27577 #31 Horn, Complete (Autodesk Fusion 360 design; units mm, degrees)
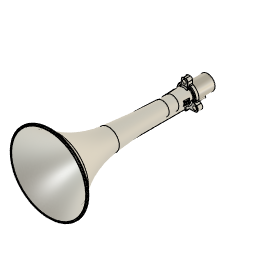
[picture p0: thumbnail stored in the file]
parameter "Bolt_Hole_Tolerance" = 1.5875 (= "( 1 / 16 ) * 1 in")
parameter "Dowel_Hole_Tolerance" = 0.0248 (= "( 1 / 1024 ) * 1 in")
parameter "d211" = 0.1984 (= "( 1 / 128 ) * 1 in")
canvas "Canvas1"
canvas "Canvas5"
canvas "Canvas7"
sketch "Main Profile" plane through (0, 0, 0) normal (1, 0, 0) x axis (0, 1, 0)
  line L1 (0, -22.225) -> (0, 22.225)
  line L2 (-53.975, 22.225) -> (0, 22.225)
  line L3 (-53.975, 44.45) -> (-53.975, 22.225)
  line L4 (-469.1063, 0) -> (0, 0)
  line L5 (-68.2625, 44.45) -> (-53.975, 44.45)
  line L6 (-53.975, -22.225) -> (0, -22.225)
  line L7 (-53.975, 22.225) -> (-53.975, -22.225)
  line L8 (-53.975, -38.1) -> (-53.975, -22.225)
  line L9 (-68.2625, -38.1) -> (-53.975, -38.1)
  line L10 (-68.2625, 44.45) -> (-68.2625, -38.1)
  line L11 (-133.2599, 16.9308) -> (0, 11.1125)
  line L12 (-63.5, 28.575) -> (-53.975, 28.575)
  line L13 (-63.5, 17.063) -> (-63.5, 28.575)
  line L14 (-133.1214, 20.1027) -> (-63.5, 17.063)
  line L15 (-469.1063, -114.3) -> (-469.1063, 114.3)
  line L16 (-68.2625, 17.2709) -> (-68.2625, 44.45)
  line L17 (9.1828, 34.925) -> (-68.2625, 34.925)
  line L18 (-34.1313, 22.225) -> (-34.1313, -22.225)
  line L19 (-133.2599, -16.9308) -> (0, -11.1125)
  line L20 (-68.2625, -17.2709) -> (-68.2625, -38.1)
  line L21 (-68.2625, -17.2709) -> (-133.1214, -20.1027)
  line L22 (-464.3438, 114.3) -> (-469.1063, 114.3)
  line L23 (-464.3438, 109.7849) -> (-464.3438, 114.3)
  line L24 (-104.775, 20.1844) -> (-63.5, 22.225)
  line L25 (-292.2803, 0) -> (-292.2803, 28.575)
  line L26 (-314.4904, -34.925) -> (-68.2625, -34.925)
  arc A1 centre (-15.2071, 2720.7853) radius 2706.4304 clockwise from (-133.2599, 16.9308) to (-292.2803, 28.575)
  arc A2 centre (-261.4012, 328.6152) radius 301.625 clockwise from (-292.2803, 28.575) to (-469.1063, 109.9002)
  arc A3 centre (-15.2071, 2720.7853) radius 2703.2554 clockwise from (-133.1214, 20.1027) to (-291.9553, 31.7333)
  arc A4 centre (-261.4012, 328.6152) radius 298.45 clockwise from (-291.9553, 31.7333) to (-469.1063, 114.3)
  arc A5 centre (-261.4012, -328.6152) radius 298.45 clockwise from (-469.1063, -114.3) to (-291.9553, -31.7333)
  arc A6 centre (-261.4012, -328.6152) radius 301.625 clockwise from (-469.1063, -109.9002) to (-292.2803, -28.575)
  arc A7 centre (-15.2071, -2720.7853) radius 2703.2554 clockwise from (-291.9553, -31.7333) to (-133.1214, -20.1027)
  arc A8 centre (-15.2071, -2720.7853) radius 2706.4304 clockwise from (-292.2803, -28.575) to (-133.2599, -16.9308)
  arc A9 centre (-119.8256, 324.6126) radius 304.8 clockwise from (-104.775, 20.1844) to (-133.1207, 20.1027)
  point P4 (0, 0)
  point P1 (0, 0)
  point P7 (0, 0)
  point P13 (0, 11.1125)
  point P15 (-53.975, 28.575)
  point P21 (-469.1063, 0)
  point P8 (-469.1063, 0)
  point P22 (-68.2625, 17.2709)
  point P23 (-68.2625, 34.925)
  point P27 (-469.1063, 109.9002)
  point P19 (-469.1063, 114.3)
  point P31 (-469.1063, 114.3)
  point P33 (-34.1313, -22.225)
  point P34 (-34.1313, 22.225)
  point P45 (0, -11.1125)
  point P14 (-133.2599, 16.9308)
  point P44 (-133.2599, -16.9308)
  point P18 (-133.1214, 20.1027)
  point P42 (-133.1214, -20.1027)
  point P25 (-292.2803, 28.575)
  point P40 (-292.2803, -28.575)
  point P39 (-469.1063, -109.9002)
  point P29 (-291.9553, 31.7333)
  point P37 (-291.9553, -31.7333)
  point P36 (-469.1063, -114.3)
  point P46 (-68.2625, -17.2709)
  point P48 (-464.3438, 109.7849)
  point P49 (-63.5, 22.225)
  point P51 (-104.775, 20.1844)
  point P54 (-292.2803, 0)
  point P50 (-104.775, 20.1844)
  point P52 (-133.1207, 20.1027)
  point P55 (-68.2625, -34.925)
  point P56 (-314.4904, -34.925)
  point P2 (0, 22.225)
  point P5 (-53.975, 22.225)
  point P3 (0, -22.225)
  point P6 (-53.975, 44.45)
  point P9 (-68.2625, 44.45)
  point P16 (-63.5, 28.575)
  point P20 (-469.1063, -114.3)
  point P47 (-464.3438, 114.3)
  point P12 (-68.2625, -38.1)
  vertical L1
  coincident L1 P4
  coincident P1 P4
  midpoint P1 L1
  perpendicular L1 L2
  perpendicular L2 L3
  coincident P1 P7
  perpendicular L1 L4
  perpendicular L3 L5
  perpendicular L1 L6
  vertical L7
  perpendicular L6 L8
  perpendicular L8 L9
  vertical L10
  coincident L1 P13
  coincident L3 P15
  perpendicular L3 L12
  perpendicular L12 L13
  parallel L11 L14
  vertical L15
  midpoint L15 P21
  coincident P8 P21
  coincident L14 P22
  coincident L10 P22
  coincident L10 P23
  perpendicular L16 L17
  tangent L11 A1
  coincident L15 P27
  tangent A1 A2
  tangent L14 A3
  concentric A1 A3
  tangent A3 A4
  concentric A2 A4
  coincident P19 P31
  coincident L6 P33
  coincident L2 P34
  perpendicular L2 L18
  symmetric L4 P13 P45
  symmetric L4 P14 P44
  symmetric L4 P18 P42
  symmetric L4 P25 P40
  symmetric L4 A1 A8
  symmetric L4 P27 P39
  symmetric L4 A2 A6
  symmetric L4 P29 P37
  symmetric L4 A3 A7
  symmetric L4 P31 P36
  symmetric L4 A4 A5
  coincident L10 P46
  perpendicular L9 L20
  tangent A7 L21
  perpendicular L15 L22
  coincident A4 P48
  vertical L23
  coincident L13 P49
  tangent L24 A9
  coincident L24 P51
  coincident L4 P54
  perpendicular L4 L25
  coincident P50 P51
  tangent L14 A9
  coincident A3 P52
  tangent A3 A9
  coincident L10 P55
  perpendicular L20 L26
  coincident A5 P56
  dimension "d1" distance P2 P5 = 53.975 (= "2 1/8")
  dimension "d2" distance P2 P3 = 44.45 (= "1 3/4")
  dimension "d3" distance P6 L4 = 44.45 (= "1 3/4")
  dimension "d4" distance P6 P9 = 14.2875 (= "( 9 / 16 ) * 1 in")
  dimension "d5" distance L4 L9 = 38.1
  dimension "d6" distance P4 P13 = 11.1125 (= "( 7 / 16 ) * 1 in")
  dimension "d7" distance L11 L14 = 3.175 (= "( 1 / 8 ) * 1 in")
  dimension "d9" distance P15 P16 = 9.525 (= "( 3 / 8 ) * 1 in")
  dimension "d10" distance L4 L12 = 28.575
  dimension "d11" distance L4 L17 = 34.925 (= "1 3/8")
  dimension "d12" distance P19 P20 = 228.6
  dimension "d17" distance L1 L18 = 34.1313 (= "1 11/32")
  dimension "d68" distance P19 P47 = 4.7625 (= "( 3 / 16 ) * 1 in")
  dimension "d114" distance P16 P49 = 6.35 (= "( 1 / 4 ) * 1 in")
  dimension "d115" distance L13 P50 = 41.275 (= "1 5/8")
  dimension "d116" radius A9 = 304.8
  dimension "d157" distance L15 L18 = 434.975 (= "17 1/8")
  dimension "d172" angle L4 L11 = 2.5
  dimension "d173" radius A2 = 301.625 (= "11 7/8")
  dimension "d174" distance P25 P54 = 28.575 (= "1 1/8")
  dimension "d175" distance P12 P55 = 3.175 (= "( 1 / 8 ) * 1 in")
revolve "Revolve1" sketch "Main Profile" AlongAngle 360
revolve "Revolve3" sketch "Main Profile" AlongAngle 360
fillet "Fillet16" radius 101.6
sketch "Flange Profile" plane through (0, -53.975, 0) normal (0, 1, 0) x axis (-1, 0, 0)
  line L1 (0, 34.925) -> (0, 0)
  line L2 (0, 44.45) -> (0, 34.925)
  line L3 (3.175, 44.45) -> (-3.175, 44.45)
  line L4 (9.525, 31.1085) -> (9.525, 38.1)
  line L5 (-30.2459, -17.4625) -> (0, 0)
  line L6 (30.2459, -17.4625) -> (0, 0)
  line L7 (30.2459, -26.9875) -> (15.0812, -26.9875)
  line L8 (29.9633, -6.3008) -> (35.0084, -9.2136)
  line L9 (0, -31.75) -> (0, 0)
  line L10 (0, -38.1) -> (0, -31.75)
  line L11 (3.9688, -38.1) -> (-3.9688, -38.1)
  line L12 (15.0812, -26.9875) -> (3.9688, -38.1)
  line L13 (-15.0812, -26.9875) -> (-3.9688, -38.1)
  line L14 (-30.2459, -26.9875) -> (-15.0812, -26.9875)
  line L15 (-29.9633, -6.3008) -> (-35.0084, -9.2136)
  line L16 (-9.525, 31.1085) -> (-9.525, 38.1)
  line L17 (9.525, 20.0805) -> (9.525, 31.1085)
  line L18 (-9.525, 20.0805) -> (-9.525, 31.1085)
  line L19 (22.1527, -1.7913) -> (29.9633, -6.3008)
  line L20 (-22.1527, -1.7913) -> (-29.9633, -6.3008)
  circle C1 centre (0, 0) radius 22.225
  circle C2 centre (0, 0) radius 28.575
  circle C3 centre (0, 34.925) radius 5.5563
  arc A1 centre (3.175, 38.1) radius 6.35 clockwise from (3.175, 44.45) to (9.525, 38.1)
  arc A2 centre (15.875, 31.1085) radius 6.35 clockwise from (12.9886, 25.4524) to (9.525, 31.1085)
  arc A3 centre (0, 0) radius 28.575 clockwise from (12.9886, 25.4524) to (28.3957, -3.196)
  circle C4 centre (-30.2459, -17.4625) radius 5.5563
  circle C5 centre (30.2459, -17.4625) radius 5.5563
  arc A4 centre (30.2459, -17.4625) radius 9.525 clockwise from (35.0084, -9.2136) to (30.2459, -26.9875)
  arc A5 centre (31.5508, -3.5512) radius 3.175 clockwise from (29.9633, -6.3008) to (28.3957, -3.196)
  circle C6 centre (0, -31.75) radius 3.9688
  arc A6 centre (-30.2459, -17.4625) radius 9.525 clockwise from (-30.2459, -26.9875) to (-35.0084, -9.2136)
  arc A7 centre (-31.5508, -3.5512) radius 3.175 clockwise from (-28.3957, -3.196) to (-29.9633, -6.3008)
  arc A8 centre (0, 0) radius 28.575 clockwise from (-28.3957, -3.196) to (-12.9886, 25.4524)
  arc A9 centre (-15.875, 31.1085) radius 6.35 clockwise from (-9.525, 31.1085) to (-12.9886, 25.4524)
  arc A10 centre (-3.175, 38.1) radius 6.35 clockwise from (-9.525, 38.1) to (-3.175, 44.45)
  point P1 (0, 0)
  point P3 (0, 0)
  point P4 (0, 34.925)
  point P5 (0, 34.925)
  point P6 (0, 34.925)
  point P10 (0, 44.45)
  point P7 (0, 44.45)
  point P30 (0, 0)
  point P31 (0, -31.75)
  point P32 (0, -31.75)
  point P33 (0, -31.75)
  point P37 (0, -38.1)
  point P34 (0, -38.1)
  point P9 (3.175, 44.45)
  point P52 (-3.175, 44.45)
  point P11 (9.525, 38.1)
  point P50 (-9.525, 38.1)
  point P13 (9.525, 31.1085)
  point P49 (-9.525, 31.1085)
  point P14 (12.9886, 25.4524)
  point P47 (-12.9886, 25.4524)
  point P16 (28.3957, -3.196)
  point P45 (-28.3957, -3.196)
  point P24 (15.0812, -26.9875)
  point P39 (-15.0812, -26.9875)
  point P25 (30.2459, -26.9875)
  point P40 (-30.2459, -26.9875)
  point P26 (35.0084, -9.2136)
  point P42 (-35.0084, -9.2136)
  point P28 (29.9633, -6.3008)
  point P43 (-29.9633, -6.3008)
  point P36 (3.9688, -38.1)
  point P38 (-3.9688, -38.1)
  point P53 (9.525, 20.0805)
  point P54 (-9.525, 20.0805)
  point P55 (22.1527, -1.7913)
  point P56 (-22.1527, -1.7913)
  point P35 (-3.9688, -38.1)
  point P19 (0, 0)
  coincident P1 P3
  vertical L1
  coincident P4 P5
  coincident P5 P6
  parallel L1 L2
  horizontal L3
  coincident L3 P10
  midpoint L3 P10
  coincident P7 P10
  tangent L3 A1
  vertical L4
  tangent A1 L4
  tangent L4 A2
  tangent A2 A3
  concentric C1 A3
  horizontal L7
  tangent L7 A4
  concentric C5 A4
  tangent A4 L8
  tangent L8 A5
  tangent A3 A5
  coincident P1 P30
  vertical L9
  coincident P31 P32
  coincident P32 P33
  parallel L9 L10
  horizontal L11
  midpoint L11 P37
  coincident P34 P37
  symmetric L1 P9 P52
  symmetric L1 P11 P50
  symmetric L1 A1 A10
  symmetric L1 P13 P49
  symmetric L1 P14 P47
  symmetric L1 A2 A9
  symmetric L1 P16 P45
  symmetric L1 A3 A8
  symmetric L1 P24 P39
  symmetric L1 P25 P40
  symmetric L1 P26 P42
  symmetric L1 A4 A6
  symmetric L1 P28 P43
  symmetric L1 A5 A7
  symmetric L1 P36 P38
  coincident C1 P53
  tangent A2 L17
  tangent A9 L18
  coincident C1 P54
  coincident C1 P55
  tangent A5 L19
  coincident C1 P56
  tangent A7 L20
  dimension "d95" distance P3 P4 = 34.925 (= "1 3/8")
  dimension "d96" diameter C3 = 11.1125 (= "( 3 / 8 ) * 1 in + Bolt_Hole_Tolerance")
  dimension "d97" radius A1 = 6.35 (= "( 1 / 4 ) * 1 in")
  dimension "d98" distance P1 L3 = 44.45 (= "1 3/4")
  dimension "d99" distance P5 L4 = 9.525 (= "( 3 / 8 ) * 1 in")
  dimension "d100" radius A2 = 6.35 (= "( 1 / 4 ) * 1 in")
  dimension "d101" radius A3 = 28.575 (= "1 1/8")
  dimension "d104" radius A4 = 9.525 (= "( 3 / 8 ) * 1 in")
  dimension "d105" angle L7 L8 = 30
  dimension "d106" radius A5 = 3.175 (= "( 1 / 8 ) * 1 in")
  dimension "d107" distance P30 P31 = 31.75 (= "1 1/4")
  dimension "d108" diameter C6 = 7.9375 (= "( 5 / 16 ) * 1 in")
  dimension "d109" distance P35 P36 = 7.9375 (= "( 5 / 16 ) * 1 in")
  dimension "d110" angle L7 L12 = 135
  dimension "d111" distance P19 L11 = 38.1 (= "1 1/2")
  dimension "d103" C-Pattern1-Angle = 360
extrude "Extrude2" add sketch "Flange Profile" profile of C1 C2 C3 L3 A1 L4 C4 C5 L7 A4 L8 C6 L11 L12 L13 L14 A6 L15 L16 A10 L17 L18 L19 L20 against normal blind 14.2875 (magnitude of "( -9 / 16 ) * 1 in")
delete_face "DeleteFace8"
extrude "Extrude6" add sketch "Main Profile" profile of A5 A7 L20 L21 L26 along normal blind 3.175 (= "( 1 / 8 ) * 1 in")
mirror "Mirror5" mirrorStitchTolerance 0.1016
delete_face "DeleteFace11"
delete_face "DeleteFace12"
fillet "Fillet18" radius 3.175 (= "( 1 / 8 ) * 1 in")
fillet "Fillet22" radius 76.2
fillet "Fillet23" radius 1.5875 (= "( 1 / 16 ) * 1 in")
fillet "Fillet19" radius 3.175 (= "( 1 / 8 ) * 1 in")
fillet "Fillet20" radius 1.5875 (= "( 1 / 16 ) * 1 in")
extrude "Extrude4" cut sketch "Flange Profile" profile of C3 C4 C5 against normal blind 14.3002
extrude "Extrude5" cut sketch "Flange Profile" profile of C2 C6 against normal blind 9.525 (magnitude of "( -3 / 8 ) * 1 in")
sketch "Main Profile" plane through (0, -63.5, 0) normal (0, 1, 0) x axis (-1, 0, 0)
  circle C1 centre (0, -31.75) radius 3.9687
  circle C2 centre (0, -31.75) radius 3.175
  concentric C1 C2
  dimension "d137" diameter C2 = 6.35 (= "( 1 / 4 ) * 1 in")
extrude "Extrude1" new body sketch "Main Profile" along normal blind 53.975 (= "2 1/8") bodies "27283 Orifice Pin #3"
offset_faces "OffsetFaces1"
work_plane "WorkPlane1" RotateAngle -180
sketch "Orifice & Number Profile" plane through (0, -43.2509, -35.7188) normal (0, 0, -1) x axis (1, 0, 0)
  line L1 (3.9688, -33.7259) -> (-3.9687, -33.7259)
  line L2 (3.9688, 20.2491) -> (-3.9687, 20.2491)
  line L3 (0, 20.2491) -> (0, -33.7259)
  line L4 (-22.225, -43.2509) -> (22.225, -43.2509)
  line L5 (1.5875, -9.1196) -> (1.5875, -33.7259)
  line L6 (0, -9.1196) -> (1.5875, -9.1196)
  circle C1 centre (0, -9.1196) radius 1.3891
  point P6 (0, -33.7259)
  point P7 (0, 20.2491)
  point P8 (0, -9.1196)
  point P11 (1.5875, -33.7259)
  point P13 (0, -9.1196)
  point P12 (1.5875, -9.1196)
  midpoint L1 P6
  midpoint L2 P7
  coincident L3 P8
  coincident L1 P11
  perpendicular L1 L5
  coincident L3 P13
  perpendicular L3 L6
  coincident P8 P13
  dimension "d143" diameter C1 = 2.7781 (= "( 7 / 64 ) * 1 in")
  dimension "d144" distance P8 L4 = 34.1313
  dimension "d145" distance P12 P13 = 1.5875 (= "( 1 / 16 ) * 1 in")
  dimension "d146" Text1-Height = 3.175 (= "( 1 / 8 ) * 1 in")
emboss "Emboss1" sketch "Orifice & Number Profile" Depth -0.1984 (= "( -1 / 128 ) * 1 in") Horizontal Distance 0 Vertical Distance 0 Rotation Angle 0
extrude "Extrude2" cut sketch "Orifice & Number Profile" profile of C1 against normal blind 3.175 (magnitude of "( -1 / 8 ) * 1 in")
fillet "Fillet21" radius 1.5875 (= "( 1 / 16 ) * 1 in")
fillet "Fillet24" radius 0.7937 (= "( 1 / 32 ) * 1 in")
sketch "Branding Profile 1" plane through (0, 0, 0) normal (0, 0, 1) x axis (1, 0, 0)
  line L1 (-21.8309, -71.2807) -> (-4.4402, -71.2807)
  curve K1 (-4.4402, -71.2807) -> (-4.4156, -104.775)
  line L2 (-20.1844, -104.775) -> (20.1844, -104.775)
  curve K2 (4.4156, -104.775) -> (4.4402, -71.2807)
  line L3 (4.4402, -71.2807) -> (21.8309, -71.2807)
  curve K3 (21.8309, -71.2807) -> (22.1357, -65.0091)
  line L4 (10.3702, -65.0091) -> (22.1504, -65.0091)
  curve K4 (10.3702, -65.0091) -> (10.3604, -71.2807)
  line L5 (-10.3604, -71.2807) -> (10.3604, -71.2807)
  curve K5 (-10.3604, -71.2807) -> (-10.3702, -65.0091)
  line L6 (-22.1504, -65.0091) -> (-10.3702, -65.0091)
  curve K6 (-22.1357, -65.0091) -> (-21.8309, -71.2807)
  curve K7 (4.4142, -133.1214) -> (4.4156, -104.775)
  line L7 (-20.1844, -104.775) -> (20.1844, -104.775)
  curve K8 (-4.4156, -104.775) -> (-4.4142, -133.1214)
  line L8 (-20.1027, -133.1214) -> (20.1027, -133.1214)
  curve K9 (4.5367, -291.9553) -> (4.4142, -133.1214)
  line L9 (-20.1027, -133.1214) -> (20.1027, -133.1214)
  curve K10 (-4.4142, -133.1214) -> (-4.5367, -291.9553)
  line L10 (-31.7333, -291.9553) -> (31.7333, -291.9553)
  line L11 (-20.1844, -104.775) -> (-21.8309, -71.2807)
  line L12 (-21.7878, -76.2) -> (-20.0037, -76.1192)
  line L13 (-20.0636, -114.261) -> (-21.7878, -76.2)
  line L14 (-18.2795, -114.1801) -> (-20.0636, -114.261)
  line L15 (-20.0037, -76.1192) -> (-18.2795, -114.1801)
  line L16 (-24.6635, -68.2625) -> (-34.6116, -68.2625)
  line L17 (0, 27.94) -> (0, 0)
  line L18 (20.1844, -104.775) -> (21.8309, -71.2807)
  line L19 (20.004, -76.1123) -> (21.7878, -76.2)
  line L20 (19.3804, -88.797) -> (20.004, -76.1123)
  line L21 (21.1642, -88.8847) -> (19.3804, -88.797)
  line L22 (21.7878, -76.2) -> (21.1642, -88.8847)
  line L23 (34.6116, -68.2625) -> (24.6635, -68.2625)
  line L24 (-23.6059, -193.524) -> (-21.8224, -193.6181)
  line L25 (-20.0954, -126.9415) -> (-23.6059, -193.524)
  line L26 (-18.312, -127.0355) -> (-20.0954, -126.9415)
  line L27 (-21.8224, -193.6181) -> (-18.312, -127.0355)
  arc A1 centre (-326.4605, -119.8309) radius 306.6459 clockwise from (-20.1844, -104.775) to (-20.1027, -133.1214)
  arc A2 centre (-2695.5701, -17.0534) radius 2677.9838 clockwise from (-20.1027, -133.1214) to (-31.7333, -291.9553)
  arc A3 centre (2695.5701, -17.0534) radius 2677.9838 clockwise from (31.7333, -291.9553) to (20.1027, -133.1214)
  arc A4 centre (326.4605, -119.8309) radius 306.6459 clockwise from (20.1027, -133.1214) to (20.1844, -104.775)
  point P3 (-21.8309, -71.2807)
  point P34 (-21.8309, -71.2807)
  point P21 (-20.1844, -104.775)
  point P35 (-20.1844, -104.775)
  point P25 (-20.1027, -133.1214)
  point P37 (-20.1027, -133.1214)
  point P36 (-20.1844, -104.775)
  point P39 (-20.1027, -133.1214)
  point P33 (-31.7333, -291.9553)
  point P40 (-31.7333, -291.9553)
  point P46 (-21.5895, -76.191)
  point P47 (-19.8653, -114.252)
  point P1 (0, 0)
  point P50 (0, 0)
  point P58 (21.8309, -71.2807)
  point P59 (20.1844, -104.775)
  point P57 (20.1844, -104.775)
  point P56 (20.1027, -133.1214)
  point P54 (20.1027, -133.1214)
  point P53 (31.7333, -291.9553)
  point P64 (21.5896, -76.1903)
  point P65 (20.966, -88.8749)
  point P72 (-19.8973, -126.9519)
  point P73 (-23.4077, -193.5345)
  point P43 (-21.7878, -76.2)
  point P44 (-20.0636, -114.261)
  point P42 (-20.0037, -76.1192)
  point P60 (21.7878, -76.2)
  point P63 (21.1642, -88.8847)
  point P69 (-23.6059, -193.524)
  point P70 (-20.0954, -126.9415)
  point P71 (-18.312, -127.0355)
  coincident P3 P34
  coincident P21 P35
  tangent L11 A1
  coincident P25 P37
  coincident P21 P36
  coincident P25 P39
  tangent A1 A2
  coincident P33 P40
  perpendicular L12 L13
  perpendicular L13 L14
  perpendicular L14 L15
  coincident L11 P46
  coincident L12 P46
  coincident A1 P47
  coincident L14 P47
  coincident P1 P50
  vertical L17
  symmetric P34 L17 P58
  symmetric P35 L17 P59
  symmetric P36 L17 P57
  symmetric P37 L17 P56
  symmetric A1 L17 A4
  symmetric P39 L17 P54
  symmetric P40 L17 P53
  symmetric A2 L17 A3
  perpendicular L18 L19
  perpendicular L19 L20
  perpendicular L20 L21
  perpendicular L21 L22
  coincident L18 P64
  coincident L19 P64
  coincident L18 P65
  coincident L21 P65
  perpendicular L24 L25
  perpendicular L25 L26
  perpendicular L26 L27
  coincident A1 P72
  coincident L26 P72
  coincident L24 P73
  coincident A2 P73
  dimension "d188" distance P43 P46 = 0.1984 (= "( 1 / 128 ) * 1 in")
  dimension "d189" distance P44 P47 = 0.1984 (= "d188")
  dimension "d190" distance P43 L16 = 7.9375 (= "( 5 / 16 ) * 1 in")
  dimension "d191" distance P43 P44 = 38.1 (= "1 1/2")
  dimension "d192" distance P42 P46 = 1.5875 (= "( 1 / 16 ) * 1 in")
  dimension "d198" distance L22 P64 = 0.1984 (= "( 1 / 128 ) * 1 in")
  dimension "d199" distance L18 L20 = 1.5875 (= "( 1 / 16 ) * 1 in")
  dimension "d200" distance P60 L23 = 7.9375 (= "d190")
  dimension "d201" distance P60 P63 = 12.7 (= "( 1 / 2 ) * 1 in")
  dimension "d213" distance P69 P73 = 0.1984 (= "( 1 / 128 ) * 1 in")
  dimension "d214" distance P70 P72 = 0.1984 (= "d213")
  dimension "d215" distance P47 P72 = 12.7 (= "( 1 / 2 ) * 1 in")
  dimension "d216" distance P71 P72 = 1.5875 (= "( 1 / 16 ) * 1 in")
  dimension "d217" distance L24 L26 = 66.675 (= "2 5/8")
extrude "Extrude8" add sketch "Branding Profile 1" profile of L2 L7 L8 L9 L11 A1 A2 L12 L13 L14 L15 L24 L25 L26 L27 distance 19.05 (= "( 3 / 4 ) * 1 in")
delete_face "DeleteFace13"
extrude "Extrude9" add sketch "Branding Profile 1" profile of L18 L19 L20 L21 L22 distance 9.525 (= "( 3 / 8 ) * 1 in")
fillet "Fillet27" radius 6.35 (= "( 1 / 4 ) * 1 in")
fillet "Fillet28" radius 3.175 (= "( 1 / 8 ) * 1 in")
fillet "Fillet30" radius 4.8877
fillet "Fillet31" radius 0.7937 (= "( 1 / 32 ) * 1 in")
sketch "Branding Profile 2" plane through (25.4721, -1.2522, 0) normal (0.9988, -0.0491, 0) x axis (0.0491, 0.9988, 0)
  curve K1 (-75.5941, -4.7625) -> (-75.0383, -4.2995)
  line L1 (-75.0383, 4.2995) -> (-75.0383, -4.2995)
  curve K2 (-75.0383, 4.2995) -> (-75.5941, 4.7625)
  line L2 (-87.1742, 4.7625) -> (-75.5941, 4.7625)
  curve K3 (-87.1742, 4.7625) -> (-87.7383, 4.2931)
  line L3 (-87.7383, -4.2931) -> (-87.7383, 4.2931)
  curve K4 (-87.7383, -4.2931) -> (-87.1742, -4.7625)
  line L4 (-75.5941, -4.7625) -> (-87.1742, -4.7625)
  line L5 (-75.0383, 0) -> (-87.7383, 0)
  line L6 (-87.7383, -3.175) -> (-75.0383, -3.175)
  point P10 (-87.7383, 0)
  point P11 (-75.0383, 0)
  point P12 (-75.0383, -3.175)
  point P13 (-87.7383, -3.175)
  midpoint L3 P10
  midpoint L1 P11
  coincident L1 P12
  coincident L3 P13
  perpendicular L3 L6
  dimension "d228" distance L5 L6 = 3.175 (= "( 1 / 8 ) * 1 in")
  dimension "d229" Text1-Height = 9.525
extrude "Extrude10" add sketch "Branding Profile 2" along normal blind 0.3969 (= "( 1 / 64 ) * 1 in") taper -21
sketch "Branding Profile 3" plane through (-25.188, -1.1411, 0) normal (-0.999, -0.0453, 0) x axis (0.0453, -0.999, 0)
  curve K1 (113.2359, 8.7717) -> (112.415, 9.525)
  line L1 (104.0174, 9.525) -> (112.415, 9.525)
  line L2 (75.9363, 9.525) -> (104.0174, 9.525)
  curve K2 (75.9363, 9.525) -> (75.1359, 8.7898)
  line L3 (75.1359, -8.7898) -> (75.1359, 8.7898)
  curve K3 (75.1359, -8.7898) -> (75.9363, -9.525)
  line L4 (104.0174, -9.525) -> (75.9363, -9.525)
  line L5 (112.415, -9.525) -> (104.0174, -9.525)
  curve K4 (112.415, -9.525) -> (113.2359, -8.7717)
  line L6 (113.2359, 8.7717) -> (113.2359, -8.7717)
  line L7 (98.4442, -4.2166) -> (100.7366, -4.5044)
  line L8 (93.2463, -4.6653) -> (92.2812, -4.6653)
  line L9 (95.1369, -5.0326) -> (95.1369, -1.5281)
  line L10 (93.3403, -1.131) -> (90.9524, 2.1371)
  line L11 (92.5598, 4.1584) -> (93.1259, 4.1584)
  line L12 (91.1532, -2.0448) -> (91.1532, -5.0326)
  line L13 (94.393, 5.2738) -> (91.3413, 5.2738)
  line L14 (109.9277, -8.4438) -> (109.9277, -7.6149)
  line L15 (84.9781, -6.3626) -> (84.9781, 6.0597)
  line L16 (87.7962, -0.4801) -> (87.7962, 0.0594)
  line L17 (86.9681, -0.9636) -> (87.3127, -0.9636)
  line L18 (86.4846, -4.4596) -> (86.4846, -1.4472)
  line L19 (108.6297, -0.592) -> (108.6297, 0.1613)
  line L20 (101.0663, -4.8781) -> (101.0663, -5.6373)
  line L21 (109.3111, 9.0165) -> (106.1747, 7.6922)
  line L22 (102.4928, -6.1011) -> (102.4928, 6.0639)
  line L23 (87.3217, -5.0926) -> (88.9649, -4.6273)
  line L24 (89.5846, -5.0959) -> (89.5846, -5.528)
  line L25 (107.579, 6.6498) -> (109.6042, 7.5049)
  line L26 (87.3543, 4.6563) -> (88.6893, 4.3319)
  line L27 (88.9427, 5.7567) -> (85.6196, 6.5641)
  line L28 (89.2038, -6.0315) -> (85.8108, -6.9922)
  line L29 (108.253, 0.5379) -> (107.7255, 0.5379)
  line L30 (100.6427, -6.011) -> (97.2673, -5.5871)
  line L31 (107.3489, -5.948) -> (107.3489, -1.3453)
  line L32 (96.6079, -4.8397) -> (96.6079, 5.1103)
  line L33 (93.6304, -4.2813) -> (93.6304, -2.0198)
  line L34 (93.505, 3.8359) -> (93.5982, 3.2617)
  line L35 (102.7468, 6.42) -> (103.5001, 6.6793)
  line L36 (107.7255, -0.9686) -> (108.253, -0.9686)
  line L37 (103.9994, 6.3232) -> (103.9994, -6.3604)
  line L38 (107.3489, 0.9145) -> (107.3489, -1.3453)
  line L39 (91.5205, -1.6682) -> (91.5298, -1.6682)
  line L40 (92.1758, 3.158) -> (92.1758, 3.5592)
  line L41 (98.1144, -3.8429) -> (98.1144, 5.1103)
  line L42 (94.7876, 3.3576) -> (94.7876, 4.8791)
  line L43 (97.7378, 5.487) -> (96.9845, 5.487)
  line L44 (91.5298, -5.4092) -> (94.7603, -5.4092)
  line L45 (92.1758, 3.5592) -> (92.1758, 3.7743)
  line L46 (90.8706, 2.3877) -> (90.8706, 4.8031)
  line L47 (94.8468, -0.6393) -> (92.2593, 2.9021)
  line L48 (91.8971, -4.2813) -> (91.8971, -2.0448)
  line L49 (109.7082, -7.2726) -> (107.5684, -6.2903)
  line L50 (80.6784, 8.1969) -> (80.0581, 8.6312)
  line L51 (107.3489, 0.9145) -> (107.3489, 6.3029)
  line L52 (83.6022, -6.7697) -> (83.6022, -7.1367)
  line L53 (86.4846, 1.0264) -> (86.4846, -1.4472)
  line L54 (103.5001, -6.7165) -> (102.7468, -6.4572)
  line L55 (105.7144, -6.6138) -> (105.7144, 6.9982)
  line L56 (81.646, -6.7702) -> (82.7145, -6.2258)
  line L57 (80.8803, -6.301) -> (80.8803, 7.809)
  line L58 (87.3127, 0.5429) -> (86.9681, 0.5429)
  line L59 (109.8343, 7.8519) -> (109.8343, 8.6696)
  line L60 (86.4846, 1.0264) -> (86.4846, 3.9726)
  line L61 (83.2091, -7.7782) -> (80.495, -9.1611)
  line L62 (106.1534, -7.2984) -> (109.3939, -8.7861)
  line L63 (79.2458, -8.3956) -> (79.2458, 8.2084)
  line L64 (89.3551, 4.8553) -> (89.3551, 5.2322)
  arc A1 centre (97.7378, 5.1103) radius 0.3766 clockwise from (97.7378, 5.487) to (98.1144, 5.1103)
  arc A2 centre (97.3612, -4.8397) radius 0.7533 clockwise from (97.2673, -5.5871) to (96.6079, -4.8397)
  arc A3 centre (94.7603, -5.0326) radius 0.3766 clockwise from (95.1369, -5.0326) to (94.7603, -5.4092)
  arc A4 centre (91.5205, -2.0448) radius 0.3766 clockwise from (91.5205, -1.6682) to (91.8971, -2.0448)
  arc A5 centre (91.3413, 4.8031) radius 0.4706 clockwise from (90.8706, 4.8031) to (91.3413, 5.2738)
  arc A6 centre (92.1238, -2.0198) radius 1.5065 clockwise from (93.3403, -1.131) to (93.6304, -2.0198)
  arc A7 centre (92.6096, 3.158) radius 0.4338 clockwise from (92.2593, 2.9021) to (92.1758, 3.158)
  arc A8 centre (94.1891, 3.3576) radius 0.5986 clockwise from (94.7876, 3.3576) to (93.5982, 3.2617)
  arc A9 centre (93.6304, -1.5281) radius 1.5065 clockwise from (94.8468, -0.6393) to (95.1369, -1.5281)
  arc A10 centre (92.5598, 3.7743) radius 0.3841 clockwise from (92.1758, 3.7743) to (92.5598, 4.1584)
  arc A11 centre (98.4911, -3.8429) radius 0.3766 clockwise from (98.4442, -4.2166) to (98.1144, -3.8429)
  arc A12 centre (91.2954, 2.3877) radius 0.4248 clockwise from (90.9524, 2.1371) to (90.8706, 2.3877)
  arc A13 centre (81.4069, -6.301) radius 0.5266 clockwise from (81.646, -6.7702) to (80.8803, -6.301)
  arc A14 centre (82.8823, -7.1367) radius 0.7199 clockwise from (83.6022, -7.1367) to (83.2091, -7.7782)
  arc A15 centre (103.6227, 6.3232) radius 0.3766 clockwise from (103.5001, 6.6793) to (103.9994, 6.3232)
  arc A16 centre (107.7255, 0.9145) radius 0.3766 clockwise from (107.7255, 0.5379) to (107.3489, 0.9145)
  arc A17 centre (102.8695, -6.1011) radius 0.3766 clockwise from (102.7468, -6.4572) to (102.4928, -6.1011)
  arc A18 centre (102.8695, 6.0639) radius 0.3766 clockwise from (102.4928, 6.0639) to (102.7468, 6.42)
  arc A19 centre (85.6325, -6.3626) radius 0.6544 clockwise from (85.8108, -6.9922) to (84.9781, -6.3626)
  arc A20 centre (86.9681, -1.4472) radius 0.4835 clockwise from (86.4846, -1.4472) to (86.9681, -0.9636)
  arc A21 centre (106.4677, -6.6138) radius 0.7533 clockwise from (106.1534, -7.2984) to (105.7144, -6.6138)
  arc A22 centre (79.762, 8.2084) radius 0.5162 clockwise from (79.2458, 8.2084) to (80.0581, 8.6312)
  arc A23 centre (100.6897, -4.8781) radius 0.3766 clockwise from (100.7366, -4.5044) to (101.0663, -4.8781)
  arc A24 centre (82.9917, -6.7697) radius 0.6105 clockwise from (82.7145, -6.2258) to (83.6022, -6.7697)
  arc A25 centre (106.4677, 6.9982) radius 0.7533 clockwise from (105.7144, 6.9982) to (106.1747, 7.6922)
  arc A26 centre (107.7255, -5.948) radius 0.3766 clockwise from (107.5684, -6.2903) to (107.3489, -5.948)
  arc A27 centre (89.0976, -5.0959) radius 0.487 clockwise from (88.9649, -4.6273) to (89.5846, -5.0959)
  arc A28 centre (108.253, -0.592) radius 0.3766 clockwise from (108.6297, -0.592) to (108.253, -0.9686)
  arc A29 centre (109.5511, -8.4438) radius 0.3766 clockwise from (109.9277, -8.4438) to (109.3939, -8.7861)
  arc A30 centre (96.9845, 5.1103) radius 0.3766 clockwise from (96.6079, 5.1103) to (96.9845, 5.487)
  arc A31 centre (92.2812, -4.2813) radius 0.3841 clockwise from (92.2812, -4.6653) to (91.8971, -4.2813)
  arc A32 centre (93.2463, -4.2813) radius 0.3841 clockwise from (93.6304, -4.2813) to (93.2463, -4.6653)
  arc A33 centre (94.393, 4.8791) radius 0.3947 clockwise from (94.393, 5.2738) to (94.7876, 4.8791)
  arc A34 centre (109.5511, -7.6149) radius 0.3766 clockwise from (109.7082, -7.2726) to (109.9277, -7.6149)
  arc A35 centre (91.5298, -2.0448) radius 0.3766 clockwise from (91.1532, -2.0448) to (91.5298, -1.6682)
  arc A36 centre (91.5298, -5.0326) radius 0.3766 clockwise from (91.5298, -5.4092) to (91.1532, -5.0326)
  arc A37 centre (93.1259, 3.7743) radius 0.3841 clockwise from (93.1259, 4.1584) to (93.505, 3.8359)
  arc A38 centre (80.105, -8.3956) radius 0.8592 clockwise from (80.495, -9.1611) to (79.2458, -8.3956)
  arc A39 centre (107.7255, 6.3029) radius 0.3766 clockwise from (107.3489, 6.3029) to (107.579, 6.6498)
  arc A40 centre (89.0612, -5.528) radius 0.5233 clockwise from (89.5846, -5.528) to (89.2038, -6.0315)
  arc A41 centre (87.1882, 3.9726) radius 0.7035 clockwise from (86.4846, 3.9726) to (87.3543, 4.6563)
  arc A42 centre (87.3127, 0.0594) radius 0.4835 clockwise from (87.3127, 0.5429) to (87.7962, 0.0594)
  arc A43 centre (107.7255, -1.3453) radius 0.3766 clockwise from (107.3489, -1.3453) to (107.7255, -0.9686)
  arc A44 centre (88.8165, 4.8553) radius 0.5386 clockwise from (89.3551, 4.8553) to (88.6893, 4.3319)
  arc A45 centre (88.8153, 5.2322) radius 0.5398 clockwise from (88.9427, 5.7567) to (89.3551, 5.2322)
  arc A46 centre (108.253, 0.1613) radius 0.3766 clockwise from (108.253, 0.5379) to (108.6297, 0.1613)
  arc A47 centre (85.4971, 6.0597) radius 0.519 clockwise from (84.9781, 6.0597) to (85.6196, 6.5641)
  arc A48 centre (87.1425, -4.4596) radius 0.6578 clockwise from (87.3217, -5.0926) to (86.4846, -4.4596)
  arc A49 centre (87.3127, -0.4801) radius 0.4835 clockwise from (87.7962, -0.4801) to (87.3127, -0.9636)
  arc A50 centre (80.4068, 7.809) radius 0.4736 clockwise from (80.6784, 8.1969) to (80.8803, 7.809)
  arc A51 centre (100.6897, -5.6373) radius 0.3766 clockwise from (101.0663, -5.6373) to (100.6427, -6.011)
  arc A52 centre (109.4576, 7.8519) radius 0.3766 clockwise from (109.8343, 7.8519) to (109.6042, 7.5049)
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  point P33 (80.8803, -6.301)
  point P183 (80.8803, -6.301)
  point P94 (98.1144, -3.8429)
  point P134 (98.1144, -3.8429)
  point P133 (108.6297, -0.2154)
  point P32 (105.7144, -6.6138)
  point P142 (105.7144, -6.6138)
  tangent A22 L63
  tangent A22 L50
  tangent L50 A50
  tangent L57 A50
  vertical L57
  tangent A38 L63
  tangent A38 L61
  tangent A14 L61
  vertical L52
  tangent A14 L52
  tangent A24 L52
  tangent A24 L56
  parallel L56 L61
  tangent A13 L56
  coincident P33 P183
  tangent A13 L57
  vertical L15
  tangent L15 A47
  tangent L27 A47
  tangent L27 A45
  tangent A45 L64
  vertical L64
  tangent A44 L64
  tangent L26 A44
  parallel L26 L27
  tangent L26 A41
  vertical L60
  tangent A41 L60
  horizontal L58
  tangent A42 L58
  tangent L16 A42
  vertical L16
  tangent L16 A49
  horizontal L17
  tangent L17 A49
  tangent L17 A20
  vertical L18
  tangent L18 A20
  vertical L53
  tangent L15 A19
  tangent A19 L28
  tangent L28 A40
  vertical L24
  tangent L24 A40
  tangent L24 A27
  tangent L23 A27
  tangent L23 A48
  tangent L18 A48
  parallel L23 L28
  horizontal L13
  tangent L13 A33
  vertical L42
  tangent A33 L42
  tangent A8 L42
  tangent A8 L34
  tangent L34 A37
  tangent L11 A37
  horizontal L11
  tangent L11 A10
  vertical L45
  tangent A10 L45
  tangent A5 L13
  vertical L46
  tangent A5 L46
  tangent A12 L46
  tangent L10 A12
  parallel L40 L45
  tangent A7 L40
  tangent A7 L47
  parallel L10 L47
  tangent A9 L47
  vertical L9
  tangent L9 A9
  tangent A6 L10
  tangent A6 L33
  vertical L33
  tangent A3 L9
  horizontal L44
  tangent A3 L44
  tangent L44 A36
  vertical L12
  tangent L12 A36
  tangent L12 A35
  horizontal L39
  tangent L39 A35
  tangent A4 L39
  vertical L48
  tangent A4 L48
  tangent A31 L48
  tangent L33 A32
  tangent L8 A31
  tangent L8 A32
  vertical L32
  tangent L32 A30
  horizontal L43
  tangent A30 L43
  tangent A1 L43
  vertical L41
  tangent A1 L41
  tangent A2 L32
  tangent A2 L30
  tangent L30 A51
  vertical L20
  tangent L20 A51
  tangent L20 A23
  tangent L7 A23
  parallel L7 L30
  tangent L7 A11
  coincident P94 P134
  tangent A11 L41
  vertical L22
  tangent A17 L22
  tangent A17 L54
  vertical L37
  tangent A15 L37
  tangent A15 L35
  tangent A18 L35
  tangent A18 L22
  tangent A25 L55
  tangent L21 A25
  vertical L59
  tangent L59 A52
  tangent L25 A52
  parallel L21 L25
  tangent L25 A39
  vertical L51
  tangent L51 A39
  tangent A16 L51
  horizontal L29
  tangent A16 L29
  tangent L29 A46
  vertical L19
  tangent L19 A46
  tangent L19 A28
  horizontal L36
  tangent A28 L36
  tangent L36 A43
  vertical L31
  tangent L31 A43
  vertical L38
  midpoint P133 L19
  tangent A26 L31
  tangent A26 L49
  tangent A34 L49
  vertical L14
  tangent L14 A34
  tangent L14 A29
  tangent A29 L62
  parallel L49 L62
  tangent A21 L62
  coincident P32 P142
  tangent A21 L55
  dimension "d357" angle L50 L63 = 55
  dimension "d359" angle L61 L63 = 63
  dimension "d367" angle L34 L42 = 9.219
  dimension "d371" radius A12 = 0.4248
  dimension "d384" distance L11 L13 = 1.1154
  dimension "d395" angle L22 L54 = 109
  dimension "d400" angle L22 L35 = 109
  dimension "d339" angle L14 L49 = 114.659
extrude "Extrude11" add sketch "Branding Profile 3" along normal blind 0.3969 (= "( 1 / 64 ) * 1 in") taper -30
sketch "Branding Profile 4" plane through (-13.3655, 0.7047, 0) normal (-0.9986, 0.0526, 0) x axis (-0.0526, -0.9986, 0)
  curve K1 (193.6654, -9.5822) -> (194.4985, -8.8448)
  line L1 (194.4985, 8.8448) -> (194.4985, -8.8448)
  curve K2 (194.4985, 8.8448) -> (193.6654, 9.5822)
  curve K3 (193.6654, 9.5822) -> (133.9665, 9.525)
  line L2 (133.3085, 9.525) -> (133.9665, 9.525)
  curve K4 (133.3085, 9.525) -> (128.6831, 9.5252)
  curve K5 (128.6831, 9.5252) -> (127.8235, 8.7446)
  line L3 (127.8235, -8.7446) -> (127.8235, 8.7446)
  curve K6 (127.8235, -8.7446) -> (128.6831, -9.5252)
  curve K7 (128.6831, -9.5252) -> (133.3085, -9.525)
  line L4 (133.9665, -9.525) -> (133.3085, -9.525)
  curve K8 (133.9665, -9.525) -> (193.6654, -9.5822)
  line L5 (194.4985, 0) -> (127.8235, 0)
  line L6 (127.8235, -3.175) -> (194.4985, -3.175)
  line L7 (161.1125, -4.7625) -> (129.0419, -4.7625)
  line L8 (161.1125, -5.9531) -> (161.1125, -4.7625)
  line L9 (129.0419, -5.9531) -> (161.1125, -5.9531)
  line L10 (129.0419, -4.7625) -> (129.0419, -5.9531)
  line L11 (129.0419, 0) -> (129.0419, -4.7625)
  line L12 (161.1125, 0) -> (161.1125, -4.7625)
  point P14 (127.8235, 0)
  point P15 (194.4985, 0)
  point P16 (194.4985, -3.175)
  point P17 (127.8235, -3.175)
  point P22 (129.0419, 0)
  point P23 (161.1125, 0)
  point P18 (129.0419, -4.7625)
  point P21 (129.0419, -5.9531)
  midpoint L3 P14
  midpoint L1 P15
  coincident L1 P16
  coincident L3 P17
  perpendicular L1 L6
  horizontal L7
  vertical L8
  horizontal L9
  vertical L10
  coincident L5 P22
  perpendicular L5 L11
  perpendicular L7 L12
  coincident L5 P23
  dimension "d242" distance L5 L6 = 3.175 (= "( 1 / 8 ) * 1 in")
  dimension "d244" distance P18 P21 = 1.1906 (= "( 3 / 64 ) * 1 in")
  dimension "d245" distance L6 L7 = 1.5875 (= "( 1 / 16 ) * 1 in")
  dimension "d243" Text1-Height = 9.525
extrude "Extrude12" add sketch "Branding Profile 4" profile of L7 L8 L9 L10 along normal blind 0.3969 (= "( 1 / 64 ) * 1 in") taper -25
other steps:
create_component "CreateComponent1"
create_component "CreateComponent2"
named bodies: "27283 Orifice Pin #3"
